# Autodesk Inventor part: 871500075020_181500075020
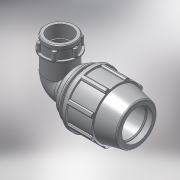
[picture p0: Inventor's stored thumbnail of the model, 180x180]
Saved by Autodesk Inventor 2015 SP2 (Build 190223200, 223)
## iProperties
Created: 2017-02
Part Number: 871500075020_181500075020
Material: PVC-Piping
Description: PLASSON 90° ELBOW FEMALE ADAPTOR 75-2"
Document SubType Name: Modeling
Designer: KIM
Mass: 92.6774 g
Surface Area: 199.44 cm^2
Volume: 66.1981 cm^3
Density: 1.4 g/cm^3
Appearance: Smooth - White
Author: KIM
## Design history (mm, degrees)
derived "87150.ipt"
feature "Solid1::87150.ipt"
tag "TaggingFeature1"
body "Solid1"
other parameters: "d2" = 75, "d4" = 16.08333, "d5" = 48.25, "d7" = 132, "d9" = 27.57143, "d11" = 6.43333, "d13" = 120 deg, "d14" = 97.5, "d15" = 12 deg, "d16" = 114.84, "d18" = 3.75, "d19" = 35 deg, "d20" = 17.5 deg, "d21" = 122.76, "d23" = 0, "d25" = 360 deg, "d27" = 2.64, "d33" = 1.5, "d42" = 71.41, "d43" = 3.96, "d46" = 2.25, "d51" = 193, "d68" = 12.86667, "d73" = 73.6528, "d75" = 84.70072, "d76" = 56.656, "d77" = 33, "d79" = 22.6624, "d80" = 1.69968, "d83" = 0, "d84" = 0, "d91" = 99, "d93" = 137, "d94" = 56.656, "d95" = 39.6592, "d96" = 12.86667, "d97" = 50 deg, "d98" = 50.9904, "d99" = 0.5, "d100" = 0.5, "d101" = 10, "d102" = 73.6528, "d103" = 25.8, "d104" = 0, "d108" = 360 deg, "d110" = 2.20958, "d111" = 8.8, "d112" = 0, "d113" = 3.21667, "d114" = 3.21667, "d115" = 111.3948, "d_" = 75, "E_" = 132, "A_" = 193, "l_" = 137, "Rp_" = 56.656, "d105" = 11.04792
